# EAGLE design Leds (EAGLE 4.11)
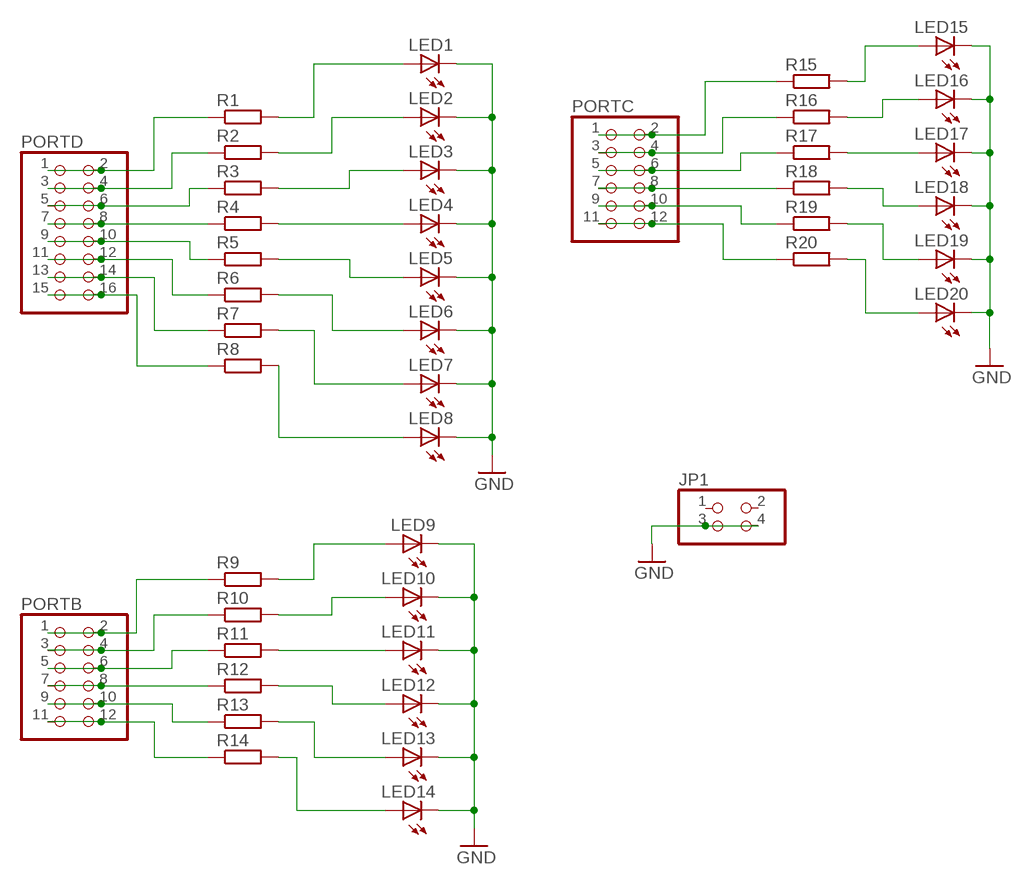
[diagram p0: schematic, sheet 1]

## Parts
JP1  PINHD-2X2  [2X02]
LED1  LED3MM  [LED3MM]
LED2  LED3MM  [LED3MM]
LED3  LED3MM  [LED3MM]
LED4  LED3MM  [LED3MM]
LED5  LED3MM  [LED3MM]
LED6  LED3MM  [LED3MM]
LED7  LED3MM  [LED3MM]
LED8  LED3MM  [LED3MM]
LED9  LED3MM  [LED3MM]
LED10  LED3MM  [LED3MM]
LED11  LED3MM  [LED3MM]
LED12  LED3MM  [LED3MM]
LED13  LED3MM  [LED3MM]
LED14  LED3MM  [LED3MM]
LED15  LED3MM  [LED3MM]
LED16  LED3MM  [LED3MM]
LED17  LED3MM  [LED3MM]
LED18  LED3MM  [LED3MM]
LED19  LED3MM  [LED3MM]
LED20  LED3MM  [LED3MM]
PORTB  PINHD-2X6  [2X06]
PORTC  PINHD-2X6  [2X06]
PORTD  PINHD-2X8  [2X08]
R1  R-EU_0204/2V  [0204V]
R2  R-EU_0204/2V  [0204V]
R3  R-EU_0204/2V  [0204V]
R4  R-EU_0204/2V  [0204V]
R5  R-EU_0204/2V  [0204V]
R6  R-EU_0204/2V  [0204V]
R7  R-EU_0204/2V  [0204V]
R8  R-EU_0204/2V  [0204V]
R9  R-EU_0204/2V  [0204V]
R10  R-EU_0204/2V  [0204V]
R11  R-EU_0204/2V  [0204V]
R12  R-EU_0204/2V  [0204V]
R13  R-EU_0204/2V  [0204V]
R14  R-EU_0204/2V  [0204V]
R15  R-EU_0204/2V  [0204V]
R16  R-EU_0204/2V  [0204V]
R17  R-EU_0204/2V  [0204V]
R18  R-EU_0204/2V  [0204V]
R19  R-EU_0204/2V  [0204V]
R20  R-EU_0204/2V  [0204V]

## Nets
GND: JP1.3 JP1.4 LED1.K(C) LED2.K(C) LED3.K(C) LED4.K(C) LED5.K(C) LED6.K(C) LED7.K(C) LED8.K(C) LED9.K(C) LED10.K(C) LED11.K(C) LED12.K(C) LED13.K(C) LED14.K(C) LED15.K(C) LED16.K(C) LED17.K(C) LED18.K(C) LED19.K(C) LED20.K(C)
N$1: PORTB.1 PORTB.2 R9.1
N$2: PORTB.3 PORTB.4 R10.1
N$3: PORTB.5 PORTB.6 R11.1
N$4: PORTB.7 PORTB.8 R12.1
N$5: PORTB.9 PORTB.10 R13.1
N$6: PORTB.11 PORTB.12 R14.1
N$7: PORTC.1 PORTC.2 R15.1
N$8: PORTC.3 PORTC.4 R16.1
N$9: PORTC.5 PORTC.6 R17.1
N$10: PORTC.7 PORTC.8 R18.1
N$11: PORTC.9 PORTC.10 R19.1
N$12: PORTC.11 PORTC.12 R20.1
N$13: PORTD.1 PORTD.2 R1.1
N$14: PORTD.3 PORTD.4 R2.1
N$15: PORTD.5 PORTD.6 R3.1
N$16: PORTD.7 PORTD.8 R4.1
N$17: PORTD.9 PORTD.10 R5.1
N$18: PORTD.11 PORTD.12 R6.1
N$19: PORTD.13 PORTD.14 R7.1
N$20: PORTD.15 PORTD.16 R8.1
N$21: LED1.A R1.2
N$22: LED2.A R2.2
N$23: LED3.A R3.2
N$24: LED4.A R4.2
N$25: LED5.A R5.2
N$26: LED6.A R6.2
N$27: LED7.A R7.2
N$28: LED8.A R8.2
N$29: LED9.A R9.2
N$30: LED10.A R10.2
N$31: LED11.A R11.2
N$32: LED12.A R12.2
N$33: LED13.A R13.2
N$34: LED14.A R14.2
N$35: LED15.A R15.2
N$36: LED16.A R16.2
N$37: LED17.A R17.2
N$38: LED18.A R18.2
N$39: LED19.A R19.2
N$40: LED20.A R20.2
Unconnected: JP1.1 JP1.2

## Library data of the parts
JP1 = pinhead:PINHD-2X2: PIN HEADER
LED1-LED20 = led:LED: LED
PORTB PORTC = pinhead:PINHD-2X6: PIN HEADER
PORTD = pinhead:PINHD-2X8: PIN HEADER
R1-R20 = rcl:R-EU_: RESISTOR, European symbol

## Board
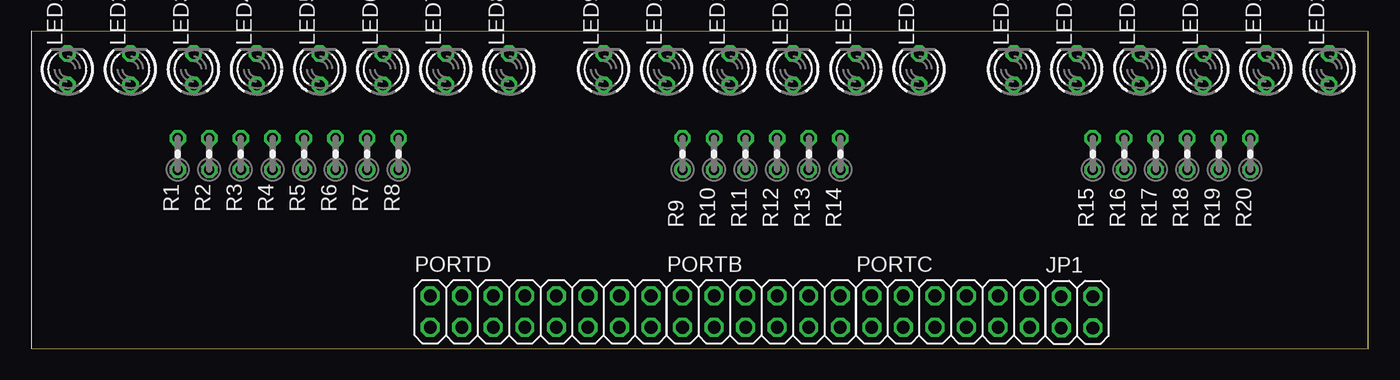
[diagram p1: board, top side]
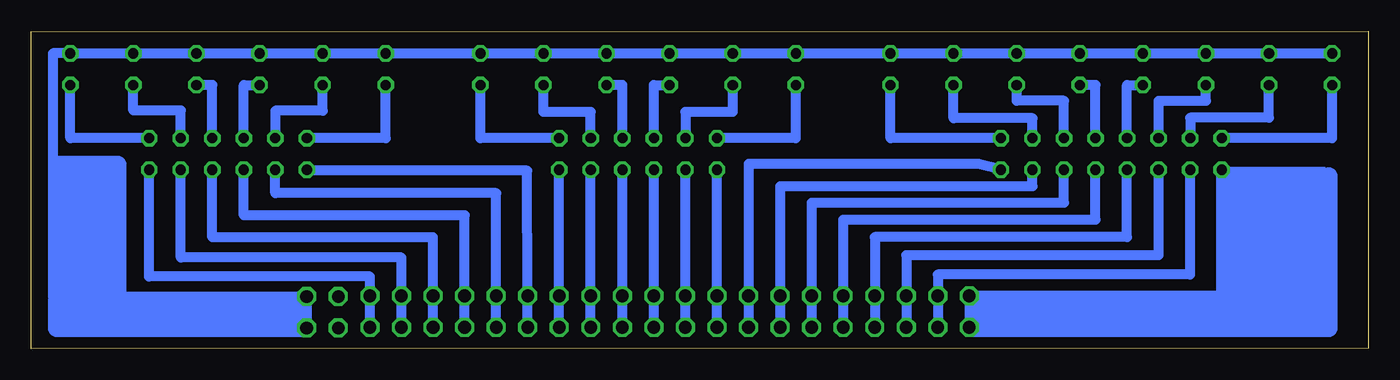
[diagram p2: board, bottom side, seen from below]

Size 107.69 x 25.62 mm. Coordinates in mm from the lower left corner, seen from the top.
Outline: 0,0.07 107.69,0 107.69,25.56 0,25.62 0,0.07
Copper layers (1*16): Top 0.035mm / dielectric 1.5mm / Bottom 0.035mm
Design rules "default": minimum track width 10mil, minimum drill 24mil, track to track 8mil, track to pad 8mil, pad to pad 8mil, via to via 8mil, smd to smd 8mil, copper to edge 40mil, drill to drill 8mil, minimum pad ring 10mil, minimum via ring 8mil, stop-mask expansion 4mil, vias tented up to drill 0mil, thermal gap 10mil

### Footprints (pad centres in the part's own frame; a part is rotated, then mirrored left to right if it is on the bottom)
2X02 = drill 1.016 octagon: 1 -1.27,-1.27; 2 -1.27,1.27; 3 1.27,-1.27; 4 1.27,1.27
LED3MM = drill 0.813 octagon: A -1.27,0; K 1.27,0
2X06 = drill 1.016 octagon: 1 -6.35,-1.27; 2 -6.35,1.27; 3 -3.81,-1.27; 4 -3.81,1.27; 5 -1.27,-1.27; 6 -1.27,1.27; 7 1.27,-1.27; 8 1.27,1.27; 9 3.81,-1.27; 10 3.81,1.27; 11 6.35,-1.27; 12 6.35,1.27
2X08 = drill 1.016 octagon: 1 -8.89,-1.27; 2 -8.89,1.27; 3 -6.35,-1.27; 4 -6.35,1.27; 5 -3.81,-1.27; 6 -3.81,1.27; 7 -1.27,-1.27; 8 -1.27,1.27; 9 1.27,-1.27; 10 1.27,1.27; 11 3.81,-1.27; 12 3.81,1.27; 13 6.35,-1.27; 14 6.35,1.27; 15 8.89,-1.27; 16 8.89,1.27
0204V = drill 0.813 octagon: 1 -1.27,0; 2 1.27,0

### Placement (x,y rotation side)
JP1  84.22,2.96 0 top
LED1  2.93,22.55 90 top
LED2  8.01,22.55 90 top
LED3  13.09,22.55 90 top
LED4  18.17,22.55 90 top
LED5  23.25,22.55 90 top
LED6  28.33,22.55 90 top
LED7  33.41,22.55 90 top
LED8  38.49,22.55 90 top
LED9  46.11,22.55 90 top
LED10  51.19,22.55 90 top
LED11  56.27,22.55 90 top
LED12  61.35,22.55 90 top
LED13  66.43,22.55 90 top
LED14  71.51,22.55 90 top
LED15  79.13,22.55 90 top
LED16  84.21,22.55 90 top
LED17  89.29,22.55 90 top
LED18  94.37,22.55 90 top
LED19  99.45,22.55 90 top
LED20  104.53,22.55 90 top
PORTB  58.81,3.01 0 top
PORTC  74.05,3.01 0 top
PORTD  41.03,3.01 0 top
R1  11.82,15.71 90 top
R2  14.36,15.71 90 top
R3  16.9,15.71 90 top
R4  19.44,15.71 90 top
R5  21.98,15.71 90 top
R6  24.52,15.71 90 top
R7  27.06,15.71 90 top
R8  29.6,15.71 90 top
R9  52.46,15.71 90 top
R10  55,15.71 90 top
R11  57.54,15.71 90 top
R12  60.08,15.71 90 top
R13  62.62,15.71 90 top
R14  65.16,15.71 90 top
R15  85.48,15.71 90 top
R16  88.02,15.71 90 top
R17  90.56,15.71 90 top
R18  93.1,15.71 90 top
R19  95.64,15.71 90 top
R20  98.18,15.71 90 top

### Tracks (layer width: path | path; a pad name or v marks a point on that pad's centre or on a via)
GND
  Bottom 0.406: JP1.3 | JP1.4 | 104.54,23.82 LED20.K
  Bottom 0.813: LED1.K LED2.K LED3.K LED4.K LED5.K LED6.K LED7.K LED8.K LED9.K LED10.K LED11.K LED12.K LED13.K LED14.K LED15.K LED16.K LED17.K LED18.K LED19.K LED20.K | JP1.4 JP1.3 | JP1.4 105.93,4.23 105.93,23.82 104.54,23.82
N$1
  Bottom 0.813: R9.1 PORTB.2 PORTB.1
N$2
  Bottom 0.813: R10.1 PORTB.4 PORTB.3
N$3
  Bottom 0.813: R11.1 PORTB.6 PORTB.5
N$4
  Bottom 0.813: R12.1 PORTB.8 PORTB.7
N$5
  Bottom 0.813: R13.1 PORTB.10 PORTB.9
N$6
  Bottom 0.813: R14.1 PORTB.12 PORTB.11
N$7
  Bottom 0.813: R15.1 85.51,14.37 67.73,14.37 PORTC.2 PORTC.1
N$8
  Bottom 0.813: R16.1 88.02,12.56 70.24,12.56 PORTC.4 PORTC.3
N$9
  Bottom 0.813: R17.1 90.56,10.77 72.78,10.77 PORTC.6 PORTC.5
N$10
  Bottom 0.813: R18.1 93.1,8.99 75.32,8.99 PORTC.8 PORTC.7
N$11
  Bottom 0.813: R19.1 95.64,7.36 77.86,7.36 PORTC.10 PORTC.9
N$12
  Bottom 0.813: R20.1 98.18,5.83 80.4,5.84 PORTC.12 PORTC.11
N$13
  Bottom 0.813: R1.1 11.82,4.28 PORTD.2 PORTD.1
N$14
  Bottom 0.813: R2.1 14.36,5.99 34.68,5.99 PORTD.4 PORTD.3
N$15
  Bottom 0.813: R3.1 16.9,7.54 37.22,7.54 PORTD.6 PORTD.5
N$16
  Bottom 0.813: R4.1 19.44,9.01 39.76,9.01 PORTD.8 PORTD.7
N$17
  Bottom 0.813: R5.1 21.98,10.4 42.3,10.4 PORTD.10 PORTD.9
N$18
  Bottom 0.813: R6.1 24.52,11.78 44.84,11.78 PORTD.12 PORTD.11
N$19
  Bottom 0.813: R7.1 27.06,13.09 47.38,13.09 PORTD.14 PORTD.13
N$20
  Bottom 0.813: R8.1 31.39,14.92 49.92,14.92 PORTD.16 PORTD.15
N$21
  Bottom 0.813: R1.2 2.93,16.98 LED1.A
N$22
  Bottom 0.813: LED2.A 8.01,18.64 14.36,18.64 R2.2
N$23
  Bottom 0.813: LED3.A 13.09,20.01 16.9,20.01 R3.2
N$24
  Bottom 0.813: LED4.A 19.44,21.28 R4.2
N$25
  Bottom 0.813: LED5.A 21.98,21.28 R5.2
N$26
  Bottom 0.813: LED6.A 28.33,20.01 24.52,20.01 R6.2
N$27
  Bottom 0.813: R7.2 27.06,18.6 33.41,18.6 LED7.A
N$28
  Bottom 0.813: R8.2 38.49,16.98 LED8.A
N$29
  Bottom 0.813: R9.2 46.11,16.98 LED9.A
N$30
  Bottom 0.813: LED10.A 51.19,19.1 55,19.1 R10.2
N$31
  Bottom 0.813: LED11.A 57.54,21.28 R11.2
N$32
  Bottom 0.813: LED12.A 60.08,21.28 R12.2
N$33
  Bottom 0.813: LED13.A 66.43,19.1 62.62,19.1 R13.2
N$34
  Bottom 0.813: R14.2 71.51,16.98 LED14.A
N$35
  Bottom 0.813: LED15.A 79.13,16.98 R15.2
N$36
  Bottom 0.813: LED16.A 84.21,19.2 88.02,19.2 R16.2
N$37
  Bottom 0.813: LED17.A 90.56,21.28 R17.2
N$38
  Bottom 0.813: LED18.A 93.1,21.28 R18.2
N$39
  Bottom 0.813: LED19.A 99.45,19.23 95.64,19.23 R19.2
N$40
  Bottom 0.813: LED20.A 104.53,16.98 R20.2
N$41
  Bottom 1.422: 32.15,1.66 3.21,1.66 3.21,13.95
N$42
  Bottom 1.422: 85.52,1.67 105.62,1.67 105.62,3.89
N$43
  Bottom 1.422: 100.7,4.43 100.7,14.88 105.49,14.88
(copper drawn outside any net)
  shapes: Bottom area x4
